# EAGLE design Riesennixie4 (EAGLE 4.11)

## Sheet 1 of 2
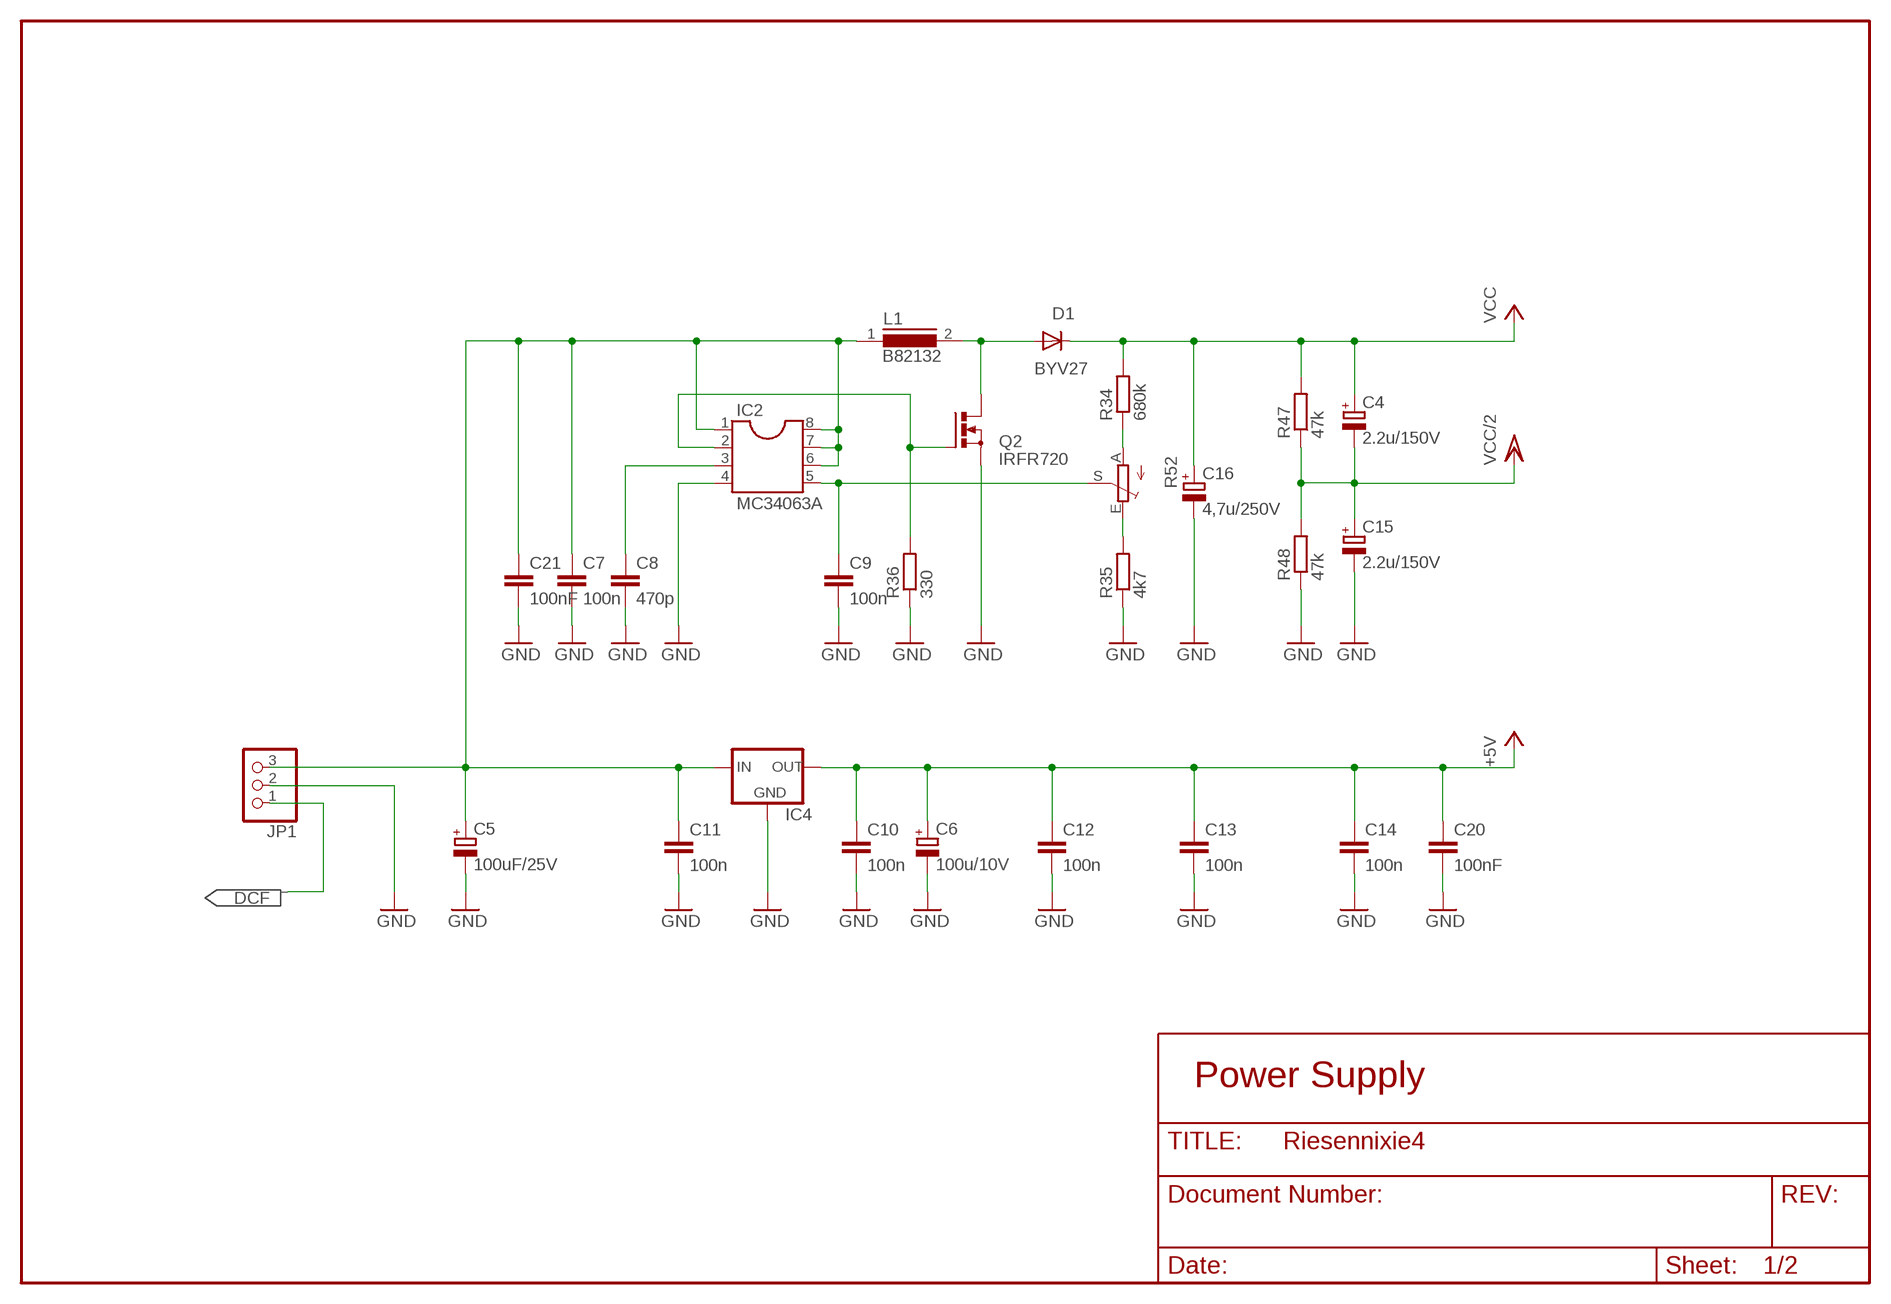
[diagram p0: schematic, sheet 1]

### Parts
C4  2.2u/150V  CPOL-EUE25-9AXIAL  [E25-9]
C5  100uF/25V  CPOL-EUE5-6  [E5-6]
C6  100u/10V  CPOL-EUE5-6  [E5-6]
C7  100n  C-EU025-024X044  [C025-024X044]
C8  470p  C-EU025-024X044  [C025-024X044]
C9  100n  C-EU025-024X044  [C025-024X044]
C10  100n  C-EU025-024X044  [C025-024X044]
C11  100n  C-EU025-024X044  [C025-024X044]
C12  100n  C-EU025-024X044  [C025-024X044]
C13  100n  C-EU025-024X044  [C025-024X044]
C14  100n  C-EU025-024X044  [C025-024X044]
C15  2.2u/150V  CPOL-EUE25-9AXIAL  [E25-9]
C16  4,7u/250V  CPOL-EUE25-10AXIAL  [E25-10]
C20  100nF  C-EU025-025X050  [C025-025X050]
C21  100nF  C-EUC1206  [C1206]
D1  BYV27  [SOD57-10]
IC2  MC34063A  DIL8  [DIL08]
IC4  78XXL  [78XXL]
JP1  PINHD-1X3  [1X03]
L1  B82132  [SUKW2-22]
Q2  IRFR720  PMOSFET_N  [TO220AHS]
R34  680k  R-EU_0204/7  [0204/7]
R35  4k7  R-EU_0204/7  [0204/7]
R36  330  R-EU_0204/7  [0204/7]
R47  47k  R-EU_0207/7  [0207/7]
R48  47k  R-EU_0207/7  [0207/7]
R52  TRIM_EU-CA6V  [CA6V]

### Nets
+5V: C6.+ C10.1 C12.1 C13.1 C14.1 C20.1 IC4.OUT ; also sheet 2
DCF: JP1.1 ; also sheet 2
GND: C5.- C6.- C7.2 C8.2 C9.2 C10.2 C11.2 C12.2 C13.2 C14.2 C15.- C16.- C20.2 C21.2 IC2.4 IC4.GND JP1.2 Q2.E(S) R35.1 R36.1 R48.1 ; also sheet 2
N$82: C8.1 IC2.3
N$83: IC2.2 Q2.B(G) R36.2
N$84: D1.A L1.2 Q2.C(D)
N$86: C9.1 IC2.5 R52.S
N$87: R34.1 R52.A
N$88: R35.2 R52.E
N$90: C5.+ C7.1 C11.1 C21.1 IC2.1 IC2.6 IC2.7 IC2.8 IC4.IN JP1.3 L1.1
VCC: C4.+ C16.+ D1.C R34.2 R47.2 ; also sheet 2
VCC/2: C4.- C15.+ R47.1 R48.2 ; also sheet 2

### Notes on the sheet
- Power Supply

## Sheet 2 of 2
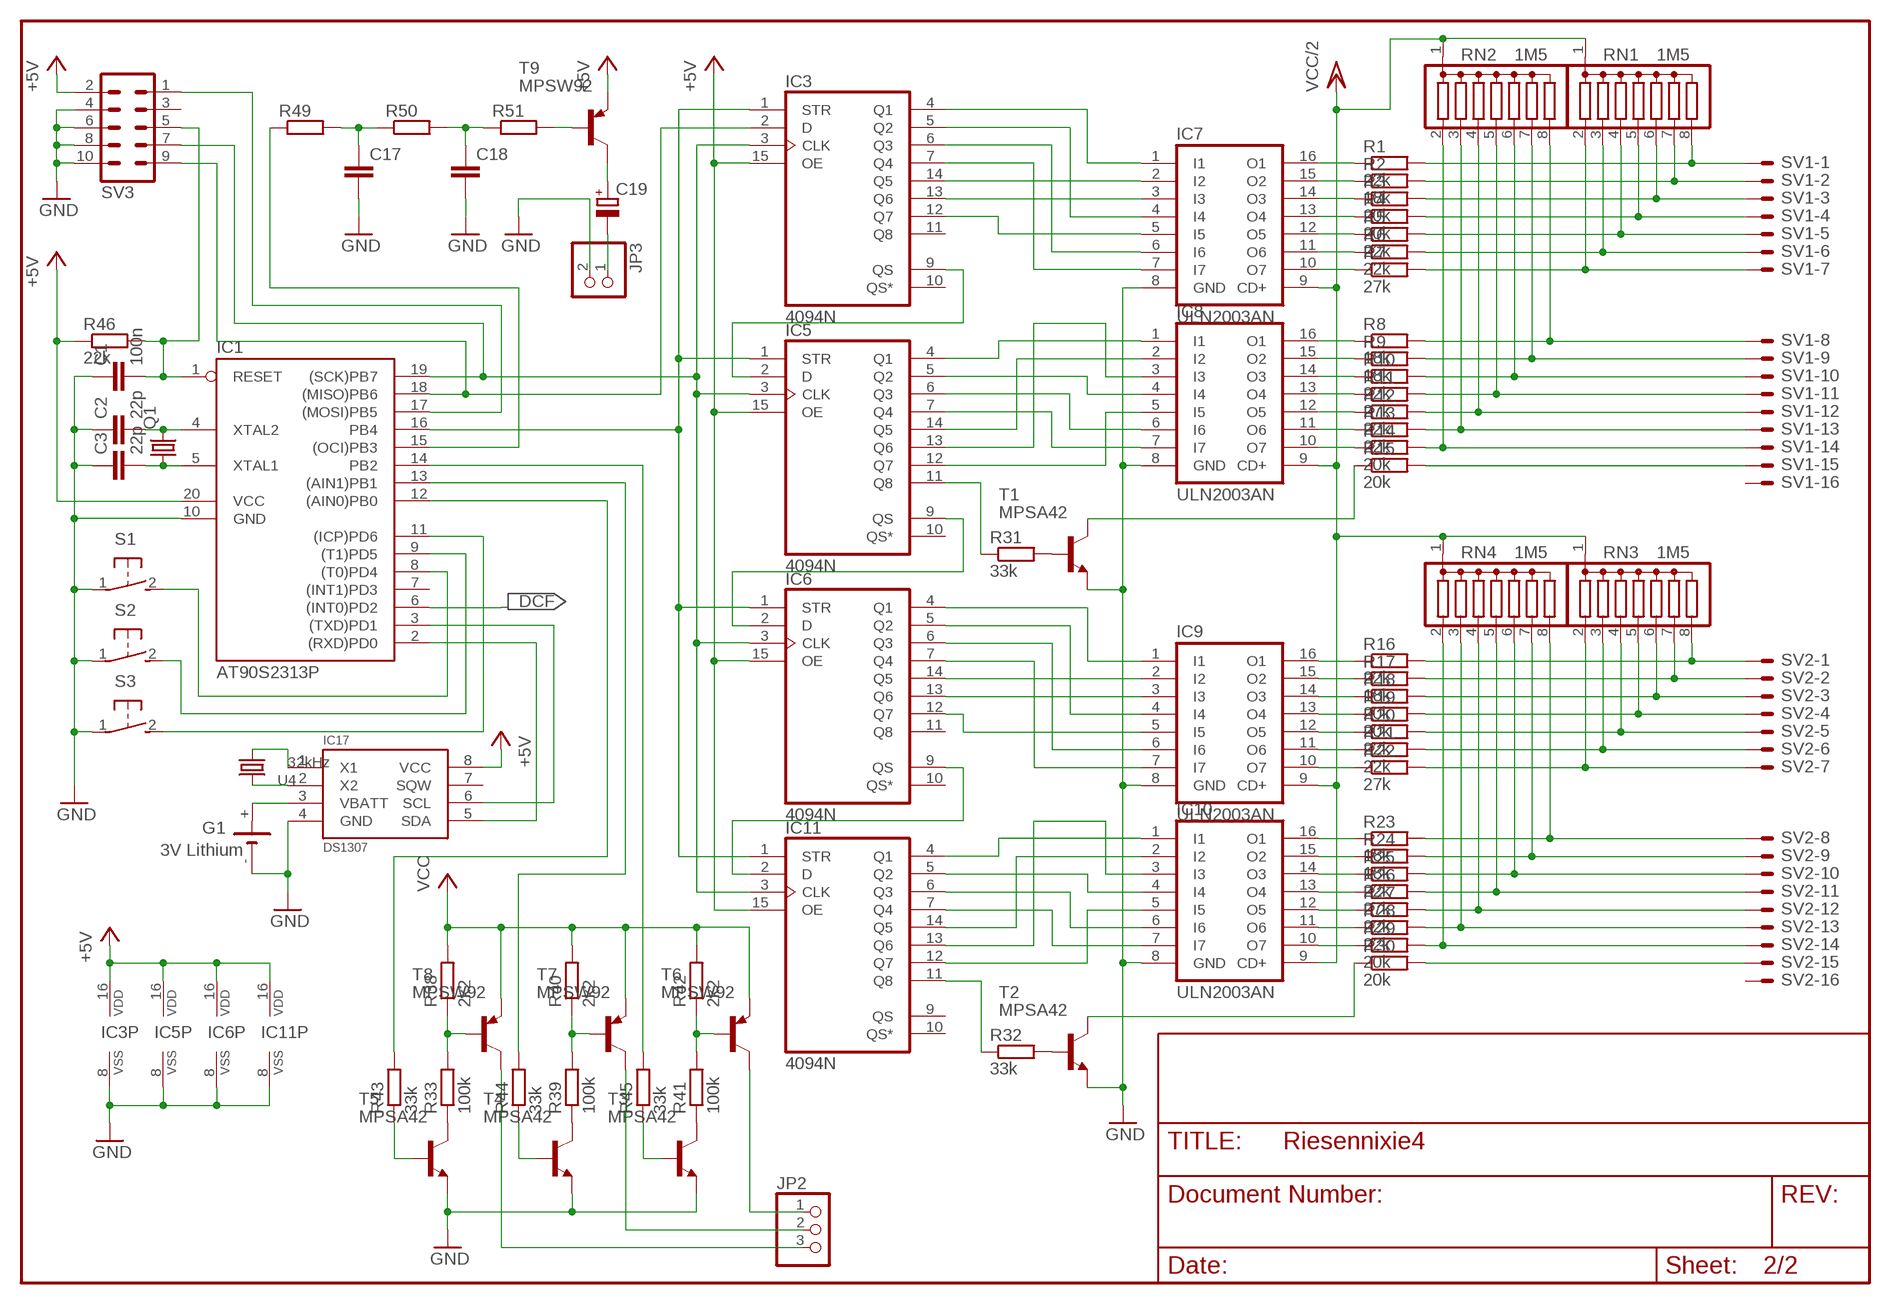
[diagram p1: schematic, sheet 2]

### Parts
C1  100n  C-EU025-025X050  [C025-025X050]
C2  22p  C-EU025-025X050  [C025-025X050]
C3  22p  C-EU025-025X050  [C025-025X050]
C17  C-EU025-025X050  [C025-025X050]
C18  C-EU025-025X050  [C025-025X050]
C19  CPOL-EUE2.5-6  [E2,5-6]
G1  3V Lithium  BR12XX  [BR12XX]
IC1  AT90S2313P  [DIL20]
IC3  4094N  [DIL16]
IC5  4094N  [DIL16]
IC6  4094N  [DIL16]
IC7  ULN2003AN  [DIL16]
IC8  ULN2003AN  [DIL16]
IC9  ULN2003AN  [DIL16]
IC10  ULN2003AN  [DIL16]
IC11  4094N  [DIL16]
IC17  DS1307  [SO08]
JP2  PINHD-1X3  [1X03]
JP3  PINHD-1X2  [1X02]
Q1  CRYTALHC49S  [HC49/S]
R1  22k  R-EU_0207/7  [0207/7]
R2  18k  R-EU_0207/7  [0207/7]
R3  20k  R-EU_0207/7  [0207/7]
R4  20k  R-EU_0207/7  [0207/7]
R5  22k  R-EU_0207/7  [0207/7]
R6  22k  R-EU_0207/7  [0207/7]
R7  27k  R-EU_0207/7  [0207/7]
R8  18k  R-EU_0207/7  [0207/7]
R9  18k  R-EU_0207/7  [0207/7]
R10  22k  R-EU_0207/7  [0207/7]
R11  27k  R-EU_0207/7  [0207/7]
R12  22k  R-EU_0207/7  [0207/7]
R13  22k  R-EU_0207/7  [0207/7]
R14  20k  R-EU_0207/7  [0207/7]
R15  20k  R-EU_0207/7  [0207/7]
R16  22k  R-EU_0207/7  [0207/7]
R17  18k  R-EU_0207/7  [0207/7]
R18  20k  R-EU_0207/7  [0207/7]
R19  20k  R-EU_0207/7  [0207/7]
R20  22k  R-EU_0207/7  [0207/7]
R21  22k  R-EU_0207/7  [0207/7]
R22  27k  R-EU_0207/7  [0207/7]
R23  18k  R-EU_0207/7  [0207/7]
R24  18k  R-EU_0207/7  [0207/7]
R25  22k  R-EU_0207/7  [0207/7]
R26  27k  R-EU_0207/7  [0207/7]
R27  22k  R-EU_0207/7  [0207/7]
R28  22k  R-EU_0207/7  [0207/7]
R29  20k  R-EU_0207/7  [0207/7]
R30  20k  R-EU_0207/7  [0207/7]
R31  33k  R-EU_0207/7  [0207/7]
R32  33k  R-EU_0207/7  [0207/7]
R33  100k  R-EU_0207/7  [0207/7]
R38  2k2  R-EU_0207/7  [0207/7]
R39  100k  R-EU_0207/7  [0207/7]
R40  2k2  R-EU_0207/7  [0207/7]
R41  100k  R-EU_0207/7  [0207/7]
R42  2k2  R-EU_0207/7  [0207/7]
R43  33k  R-EU_0204/7  [0204/7]
R44  33k  R-EU_0204/7  [0204/7]
R45  33k  R-EU_0204/7  [0204/7]
R46  22k  R-EU_0204/7  [0204/7]
R49  R-EU_0207/7  [0207/7]
R50  R-EU_0207/7  [0207/7]
R51  R-EU_0207/7  [0207/7]
RN1  1M5  G07R  [SIL8]
RN2  1M5  G07R  [SIL8]
RN3  1M5  G07R  [SIL8]
RN4  1M5  G07R  [SIL8]
S1  31-XX  [B3F-31XX]
S2  31-XX  [B3F-31XX]
S3  31-XX  [B3F-31XX]
SV1  ML16LE  [ML16L]
SV2  ML16LE  [ML16L]
SV3  ML10L  [ML10L]
T1  MPSA42  MPSA42-NPN-TO92-CBE  [TO92-CBE]
T2  MPSA42  MPSA42-NPN-TO92-CBE  [TO92-CBE]
T3  MPSA42  MPSA42-NPN-TO92-CBE  [TO92-CBE]
T4  MPSA42  MPSA42-NPN-TO92-CBE  [TO92-CBE]
T5  MPSA42  MPSA42-NPN-TO92-CBE  [TO92-CBE]
T6  MPSW92  MPSW92-PNP-TO92-CBE  [TO92-CBE]
T7  MPSW92  MPSW92-PNP-TO92-CBE  [TO92-CBE]
T8  MPSW92  MPSW92-PNP-TO92-CBE  [TO92-CBE]
T9  MPSW92  BC557B-PNP-TO92-EBC  [TO92-EBC]
U4  32kHz  TC26H  [TC26H]

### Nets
+5V: IC1.20(VCC) IC3.15(OE) IC3.16(VDD) IC5.15(OE) IC5.16(VDD) IC6.15(OE) IC6.16(VDD) IC11.15(OE) IC11.16(VDD) IC17.8(VCC) R46.1 SV3.2 T9.E ; also sheet 1
DCF: IC1.6((INT0)PD2) ; also sheet 1
GND: C1.1 C2.1 C3.1 C17.2 C18.2 G1.- IC1.10(GND) IC3.8(VSS) IC5.8(VSS) IC6.8(VSS) IC7.8(GND) IC8.8(GND) IC9.8(GND) IC10.8(GND) IC11.8(VSS) IC17.4(GND) JP3.2 S1.1(P) S2.1(P) S3.1(P) SV3.4 SV3.6 SV3.8 SV3.10 T1.E T2.E T3.E T4.E T5.E ; also sheet 1
N$1: IC7.16(O1) R1.1
N$2: IC7.15(O2) R2.1
N$3: IC7.14(O3) R3.1
N$4: IC7.13(O4) R4.1
N$5: IC7.12(O5) R5.1
N$6: IC7.11(O6) R6.1
N$7: IC7.10(O7) R7.1
N$8: IC8.16(O1) R8.1
N$9: IC8.15(O2) R9.1
N$10: IC8.14(O3) R10.1
N$11: IC8.13(O4) R11.1
N$12: IC8.12(O5) R12.1
N$13: IC8.11(O6) R13.1
N$14: IC8.10(O7) R14.1
N$15: IC9.16(O1) R16.1
N$16: IC9.15(O2) R17.1
N$17: IC9.14(O3) R18.1
N$18: IC9.13(O4) R19.1
N$19: IC9.12(O5) R20.1
N$20: IC9.11(O6) R21.1
N$21: IC9.10(O7) R22.1
N$22: IC10.16(O1) R23.1
N$23: IC10.15(O2) R24.1
N$24: IC10.14(O3) R25.1
N$25: IC10.13(O4) R26.1
N$26: IC10.12(O5) R27.1
N$27: IC10.11(O6) R28.1
N$28: IC10.10(O7) R29.1
N$29: R1.2 RN1.8 SV1.1
N$30: R2.2 RN1.7 SV1.2
N$31: R3.2 RN1.6 SV1.3
N$32: R4.2 RN1.5 SV1.4
N$33: R5.2 RN1.4 SV1.5
N$34: R6.2 RN1.3 SV1.6
N$35: R7.2 RN1.2 SV1.7
N$36: R8.2 RN2.8 SV1.8
N$37: R9.2 RN2.7 SV1.9
N$38: R10.2 RN2.6 SV1.10
N$39: R11.2 RN2.5 SV1.11
N$40: R12.2 RN2.4 SV1.12
N$41: R13.2 RN2.3 SV1.13
N$42: R14.2 RN2.2 SV1.14
N$43: R16.2 RN3.8 SV2.1
N$44: R17.2 RN3.7 SV2.2
N$45: R18.2 RN3.6 SV2.3
N$46: R19.2 RN3.5 SV2.4
N$47: R20.2 RN3.4 SV2.5
N$48: R21.2 RN3.3 SV2.6
N$49: R22.2 RN3.2 SV2.7
N$50: R23.2 RN4.8 SV2.8
N$51: R24.2 RN4.7 SV2.9
N$52: R25.2 RN4.6 SV2.10
N$53: R26.2 RN4.5 SV2.11
N$54: R27.2 RN4.4 SV2.12
N$55: R28.2 RN4.3 SV2.13
N$56: R29.2 RN4.2 SV2.14
N$57: IC3.7(Q4) IC7.7(I7)
N$58: IC3.6(Q3) IC7.6(I6)
N$59: IC3.5(Q2) IC7.4(I4)
N$60: IC3.4(Q1) IC7.1(I1)
N$61: IC3.12(Q7) IC7.5(I5)
N$62: IC3.13(Q6) IC7.3(I3)
N$63: IC3.14(Q5) IC7.2(I2)
N$64: IC5.14(Q5) IC8.2(I2)
N$65: IC5.4(Q1) IC8.1(I1)
N$66: IC5.7(Q4) IC8.7(I7)
N$67: IC5.6(Q3) IC8.6(I6)
N$68: IC5.5(Q2) IC8.4(I4)
N$69: IC5.12(Q7) IC8.5(I5)
N$70: IC5.13(Q6) IC8.3(I3)
N$71: IC6.4(Q1) IC9.1(I1)
N$72: IC6.5(Q2) IC9.4(I4)
N$73: IC6.6(Q3) IC9.6(I6)
N$74: IC6.7(Q4) IC9.7(I7)
N$75: IC6.14(Q5) IC9.2(I2)
N$76: IC6.13(Q6) IC9.3(I3)
N$77: IC6.12(Q7) IC9.5(I5)
N$78: IC10.1(I1) IC11.4(Q1)
N$79: IC10.4(I4) IC11.5(Q2)
N$80: IC10.6(I6) IC11.6(Q3)
N$81: IC10.7(I7) IC11.7(Q4)
N$85: IC10.2(I2) IC11.14(Q5)
N$89: IC10.3(I3) IC11.13(Q6)
N$91: IC10.5(I5) IC11.12(Q7)
N$92: R30.2 SV2.15
N$93: IC3.9(QS) IC5.2(D)
N$94: IC5.9(QS) IC6.2(D)
N$95: IC6.9(QS) IC11.2(D)
N$96: IC1.19((SCK)PB7) IC3.3(CLK) IC5.3(CLK) IC6.3(CLK) IC11.3(CLK) SV3.7
N$97: IC1.16(PB4) IC3.1(STR) IC5.1(STR) IC6.1(STR) IC11.1(STR)
N$98: R15.1 T1.C
N$99: R30.1 T2.C
N$100: R31.2 T1.B
N$101: R32.2 T2.B
N$102: IC5.11(Q8) R31.1
N$103: IC11.11(Q8) R32.1
N$104: R33.1 T5.C
N$105: R33.2 R38.1 T8.B
N$106: R39.1 T4.C
N$107: R39.2 R40.1 T7.B
N$108: R41.1 T3.C
N$109: R41.2 R42.1 T6.B
N$110: R43.1 T5.B
N$111: R44.1 T4.B
N$112: JP2.3 T8.C
N$113: JP2.2 T7.C
N$114: JP2.1 T6.C
N$115: R45.1 T3.B
N$116: R15.2 SV1.15
N$117: C1.2 IC1.1(RESET) R46.2 SV3.5
N$118: IC1.11((ICP)PD6) S3.2(S)
N$119: IC1.14(PB2) R45.2
N$120: IC1.13((AIN1)PB1) R44.2
N$121: IC1.12((AIN0)PB0) R43.2
N$122: IC1.18((MISO)PB6) IC3.2(D) SV3.9
N$123: IC17.2(X2) U4.2
N$124: IC1.9((T1)PD5) S2.2(S)
N$125: C2.2 IC1.4(XTAL2) Q1.2
N$126: C3.2 IC1.5(XTAL1) Q1.1
N$127: IC1.8((T0)PD4) S1.2(S)
N$128: C17.1 R49.2 R50.1
N$129: R51.2 T9.B
N$130: C18.1 R50.2 R51.1
N$131: C19.+ T9.C
N$132: C19.- JP3.1
N$133: IC1.15((OCI)PB3) R49.1
N$134: IC1.17((MOSI)PB5) SV3.1
N$135: IC17.1(X1) U4.1
N$136: G1.+ IC17.3(VBATT)
N$137: IC1.2((RXD)PD0) IC17.5(SDA)
N$138: IC1.3((TXD)PD1) IC17.6(SCL)
VCC: R38.2 R40.2 R42.2 T6.E T7.E T8.E ; also sheet 1
VCC/2: IC7.9(CD+) IC8.9(CD+) IC9.9(CD+) IC10.9(CD+) RN1.1 RN2.1 RN3.1 RN4.1 ; also sheet 1
Unconnected: IC1.7((INT1)PD3) IC3.10(QS*) IC3.11(Q8) IC5.10(QS*) IC6.10(QS*) IC6.11(Q8) IC11.9(QS) IC11.10(QS*) IC17.7(SQW) SV1.16 SV2.16 SV3.3

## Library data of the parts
C1-C3 C7-C14 C17 C18 C20 C21 = rcl:C-EU: CAPACITOR, European symbol
C4-C6 C15 C16 C19 = rcl:CPOL-EU: POLARIZED CAPACITOR, European symbol
D1 = diode:BYV27: DIODE
G1 = battery:BR12XX
IC1 = atmel:AT90S2313: MICROCONTROLLER 2 Kbytes FLASH 128 bytes SRAM 128 bytes EEPROM UART
IC2 = ic-package:DIL8: Dual In Line
IC3 IC5 IC6 IC11 = 40xx:4094: 8-stage SHIFT/STORE REGISTER, tri-state
IC4 = v-reg:78XXL: VOLTAGE REGULATOR
IC7-IC10 = uln-udn:ULN2003A: DRIVER ARRAY
IC17 = PUMP:DS1307
JP1 JP2 = pinhead:PINHD-1X3: PIN HEADER
JP3 = pinhead:PINHD-1X2: PIN HEADER
L1 = inductors:B82132: INDUCTOR
Q1 = crystal:CRYTAL: CRYSTAL
Q2 = transistor-power:PMOSFET_N: Power MOSFET N-Channel
R1-R36 R38-R51 = rcl:R-EU_: RESISTOR, European symbol
R52 = pot:TRIM_EU-: POTENTIOMETER
RN1-RN4 = resistor-sil:G07R: SIL RESISTOR
S1-S3 = switch-omron:31-XX: OMRON SWITCH
SV1 SV2 = con-harting-ml:ML16?E: HARTING
SV3 = con-harting-ml:ML10: HARTING
T1-T5 = transistor:*-NPN-: NPN Transistror
T6-T9 = transistor:*-PNP-: PNP Transistror
U4 = QUARTZ:TC26H

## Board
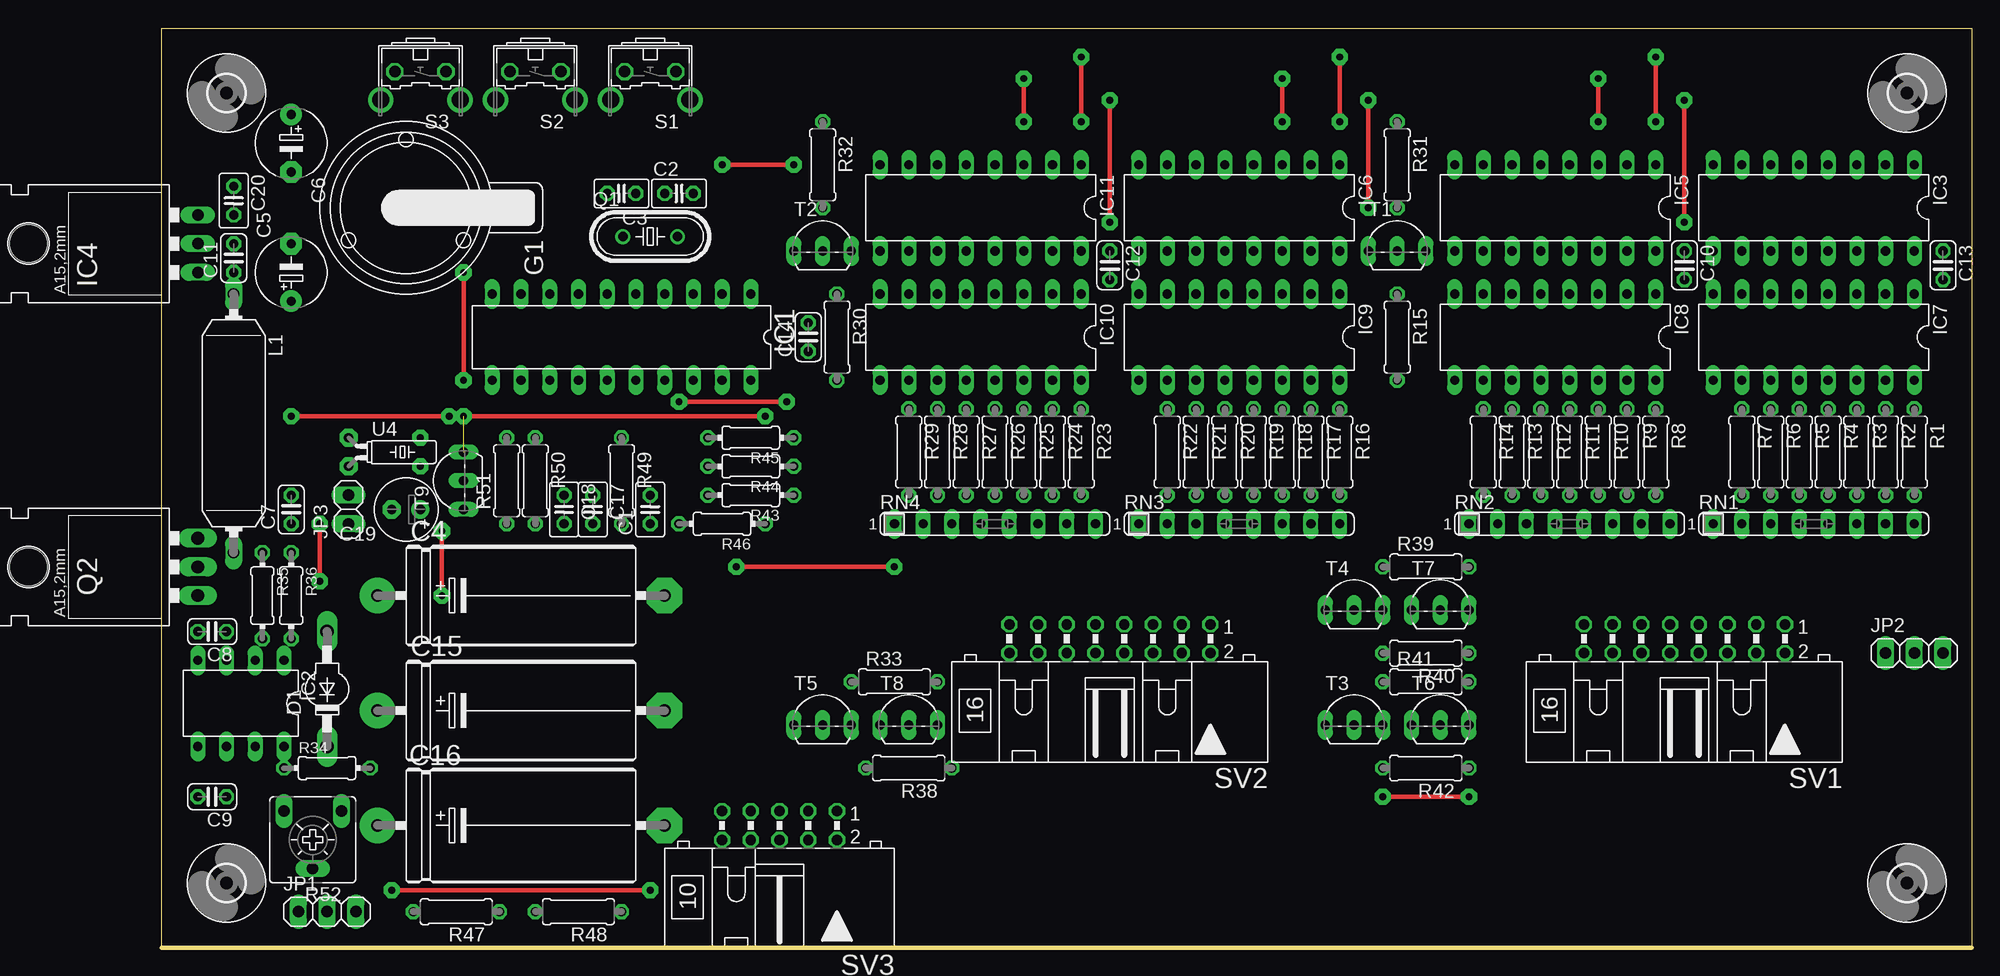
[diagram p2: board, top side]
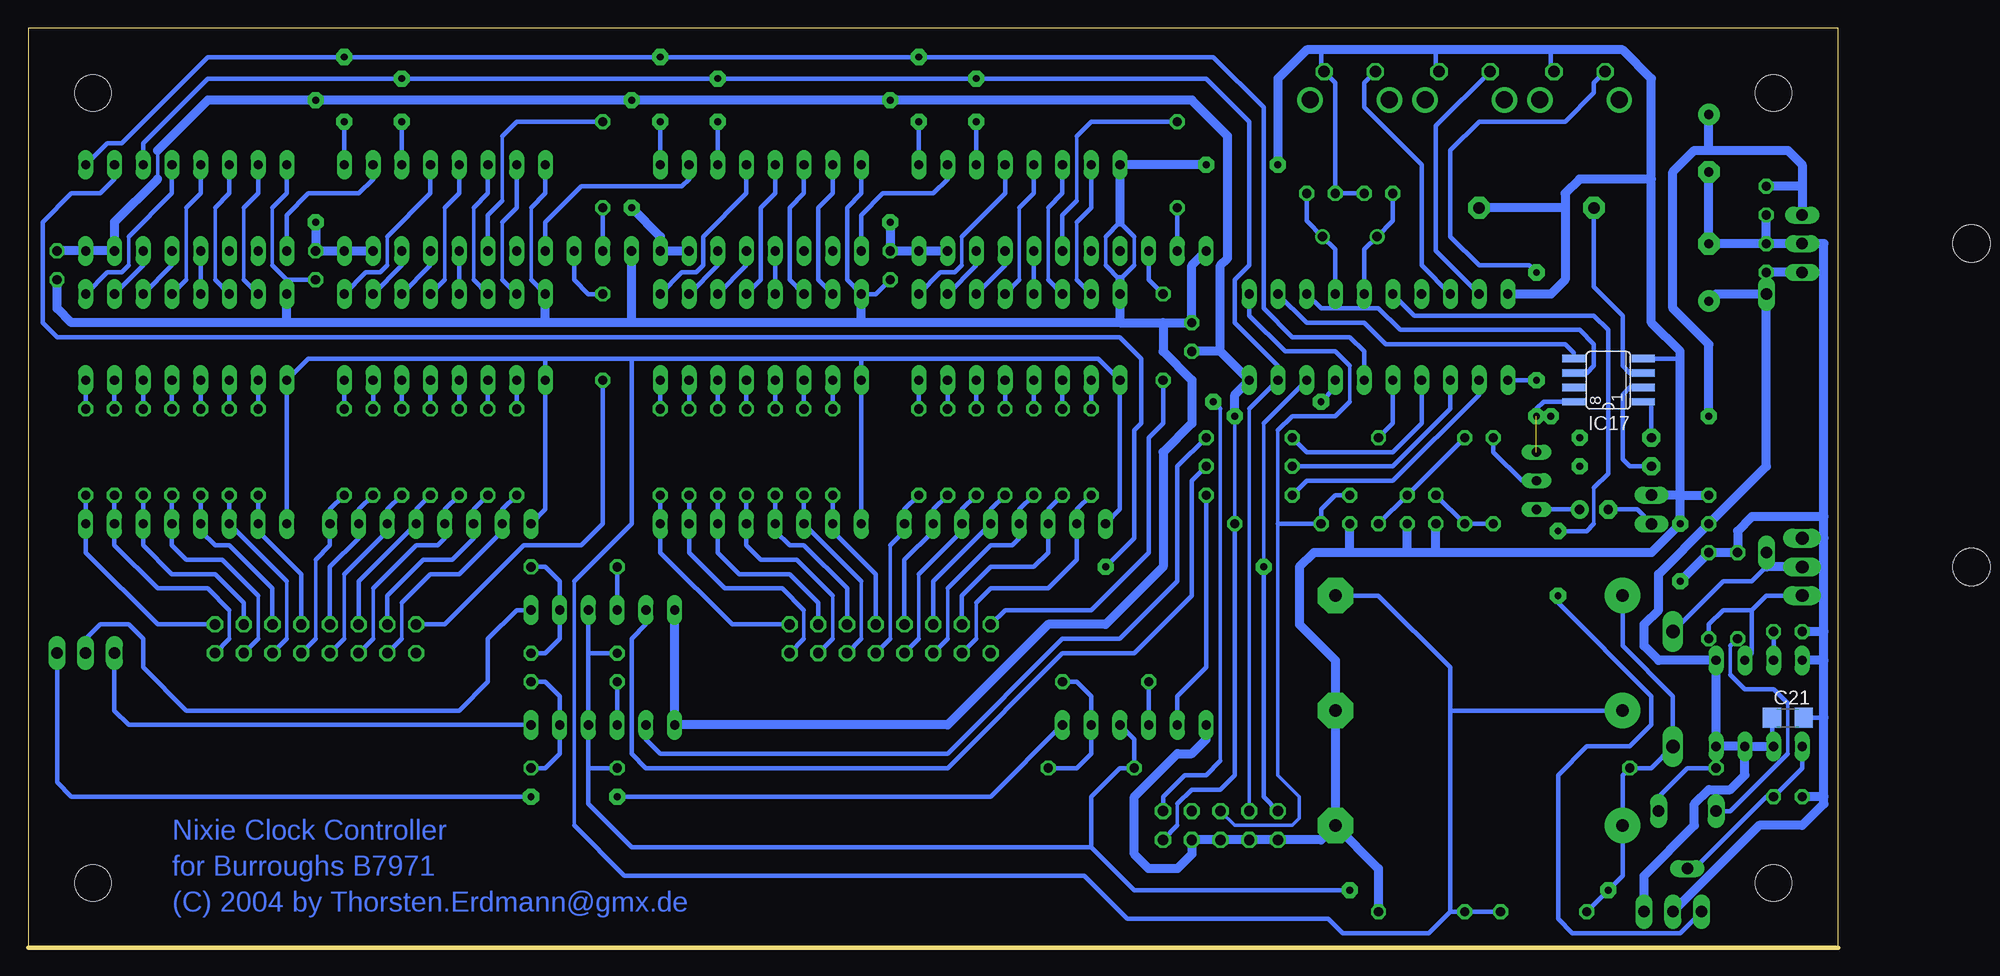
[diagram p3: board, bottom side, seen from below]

Size 160.02 x 81.28 mm. Coordinates in mm from the lower left corner, seen from the top.
Outline: 0,81.28 160.02,81.28 160.02,0 0,0 0,81.28
Copper layers (1*16): Top 0.035mm / dielectric 1.5mm / Bottom 0.035mm
Design rules "default": minimum track width 10mil, minimum drill 24mil, track to track 8mil, track to pad 8mil, pad to pad 8mil, via to via 8mil, smd to smd 8mil, copper to edge 40mil, drill to drill 8mil, minimum pad ring 10mil, minimum via ring 8mil, stop-mask expansion 4mil, vias tented up to drill 0mil, thermal gap 10mil

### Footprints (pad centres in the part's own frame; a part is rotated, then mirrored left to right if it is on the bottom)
C025-025X050 = drill 0.813 octagon: 1 -1.27,0; 2 1.27,0
E25-9 = drill 1.118 pad 3.15 round: + -12.7,0 | drill 1.118 pad 3.15 octagon: - 12.7,0
E5-6 = drill 0.813 pad 1.905 round: + -2.54,0 | drill 0.813 pad 1.905 octagon: - 2.54,0
C025-024X044 = drill 0.813 octagon: 1 -1.27,0; 2 1.27,0
E25-10 = drill 1.118 pad 3.15 round: + -12.7,0 | drill 1.118 pad 3.15 octagon: - 12.7,0
E2,5-6 = drill 0.813 pad 1.6 round: + -1.27,0 | drill 0.813 pad 1.6 octagon: - 1.27,0
C1206 = smd 1.6 x 1.8: 1 -1.4,0; 2 1.4,0
SOD57-10 = drill 1.194 long: A 5.08,0; C -5.08,0
BR12XX = drill 1.016 pad 1.93 octagon: + 0,0; - 0,10.16
DIL20 = drill 0.813 long: 1 -11.43,-3.81; 2 -8.89,-3.81; 3 -6.35,-3.81; 4 -3.81,-3.81; 5 -1.27,-3.81; 6 1.27,-3.81; 7 3.81,-3.81; 8 6.35,-3.81; 9 8.89,-3.81; 10 11.43,-3.81; 11 11.43,3.81; 12 8.89,3.81; 13 6.35,3.81; 14 3.81,3.81; 15 1.27,3.81; 16 -1.27,3.81; 17 -3.81,3.81; 18 -6.35,3.81; 19 -8.89,3.81; 20 -11.43,3.81
DIL08 = drill 0.813 long: 1 -3.81,-3.81; 2 -1.27,-3.81; 3 1.27,-3.81; 4 3.81,-3.81; 5 3.81,3.81; 6 1.27,3.81; 7 -1.27,3.81; 8 -3.81,3.81
DIL16 = drill 0.813 long: 1 -8.89,-3.81; 2 -6.35,-3.81; 3 -3.81,-3.81; 4 -1.27,-3.81; 5 1.27,-3.81; 6 3.81,-3.81; 7 6.35,-3.81; 8 8.89,-3.81; 9 8.89,3.81; 10 6.35,3.81; 11 3.81,3.81; 12 1.27,3.81; 13 -1.27,3.81; 14 -3.81,3.81; 15 -6.35,3.81; 16 -8.89,3.81
78XXL = drill 1.016 long: GND 0,-3.81; IN -2.54,-3.81; OUT 2.54,-3.81 | hole 3.302: 0,11.176
SO08 = smd 0.66 x 2.032: 1 -1.905,-3.073; 2 -0.635,-3.073; 3 0.635,-3.073; 4 1.905,-3.073; 5 1.905,3.073; 6 0.635,3.073; 7 -0.635,3.073; 8 -1.905,3.073
1X03 = drill 1.016 long: 1 -2.54,0; 2 0,0; 3 2.54,0
1X02 = drill 1.016 long: 1 -1.27,0; 2 1.27,0
SUKW2-22 = drill 1.016 long: 1 -11.43,0; 2 11.43,0
HC49/S = drill 0.813 round: 1 -2.413,0; 2 2.413,0
TO220AHS = drill 1.118 long: B -2.54,-3.81; C 0,-3.81; E 2.54,-3.81 | hole 3.302: 0,11.176
0207/7 = drill 0.813 octagon: 1 -3.81,0; 2 3.81,0
0204/7 = drill 0.813 octagon: 1 -3.81,0; 2 3.81,0
CA6V = drill 1.016 long: A -2.54,-2.54; E 2.54,-2.54; S 0,2.54
SIL8 = drill 0.813 long: 1 -8.89,0; 2 -6.35,0; 3 -3.81,0; 4 -1.27,0; 5 1.27,0; 6 3.81,0; 7 6.35,0; 8 8.89,0
B3F-31XX = drill 1.016 octagon: 1 -2.261,-1.245; 2 2.261,-1.245 | drill 1.499 pad 2.159 round: 3 -3.505,1.245; 4 3.505,1.245
ML16L = drill 0.914 octagon: 1 -8.89,-1.27; 2 -8.89,1.27; 3 -6.35,-1.27; 4 -6.35,1.27; 5 -3.81,-1.27; 6 -3.81,1.27; 7 -1.27,-1.27; 8 -1.27,1.27; 9 1.27,-1.27; 10 1.27,1.27; 11 3.81,-1.27; 12 3.81,1.27; 13 6.35,-1.27; 14 6.35,1.27; 15 8.89,-1.27; 16 8.89,1.27
ML10L = drill 0.914 octagon: 1 -5.08,-1.27; 2 -5.08,1.27; 3 -2.54,-1.27; 4 -2.54,1.27; 5 0,-1.27; 6 0,1.27; 7 2.54,-1.27; 8 2.54,1.27; 9 5.08,-1.27; 10 5.08,1.27
TO92-CBE = drill 0.813 long: B 0,0; C 2.54,0; E -2.54,0
TO92-EBC = drill 0.813 long: B 0,-1.27; C -2.54,-1.27; E 2.54,-1.27
TC26H = drill 0.813 pad 1.6 octagon: 1 -1.27,0; 2 1.27,0
3,2 = hole 3.2: 0,0

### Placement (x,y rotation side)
C1  43.18,38.73 90 top
C2  45.72,66.68 0 top
C3  40.64,66.68 180 top
C4  31.75,31.12 0 top
C5  11.43,59.69 90 top
C6  11.43,71.12 270 top
C7  11.43,38.73 90 top
C8  4.45,27.94 180 top
C9  4.45,13.33 180 top
C10  134.62,60.32 270 top
C11  6.35,60.96 90 top
C12  83.82,60.32 270 top
C13  157.48,60.32 270 top
C14  57.15,53.98 90 top
C15  31.75,20.96 0 top
C16  31.75,10.79 0 top
C17  38.1,38.73 270 top
C18  35.56,38.73 270 top
C19  21.59,38.73 180 top
C20  6.35,66.04 270 top
C21  4.45,20.32 0 bottom
D1  14.61,22.86 90 top
G1  21.59,65.41 270 top
IC1  40.64,53.98 180 top
IC2  6.98,21.59 180 top
IC3  146.05,65.41 180 top
IC4  -0.64,62.23 90 top
IC5  123.19,65.41 180 top
IC6  95.25,65.41 180 top
IC7  146.05,53.98 180 top
IC8  123.19,53.98 180 top
IC9  95.25,53.98 180 top
IC10  72.39,53.98 180 top
IC11  72.39,65.41 180 top
IC17  20.32,50.16 90 bottom
JP1  14.61,3.17 0 top
JP2  154.94,26.04 0 top
JP3  16.51,38.73 90 top
L1  6.35,46.35 270 top
Q1  43.18,62.86 0 top
Q2  -0.64,33.66 90 top
R1  154.94,43.81 270 top
R2  152.4,43.81 270 top
R3  149.86,43.81 270 top
R4  147.32,43.81 270 top
R5  144.78,43.81 270 top
R6  142.24,43.81 270 top
R7  139.7,43.81 270 top
R8  132.08,43.81 270 top
R9  129.54,43.81 270 top
R10  127,43.81 270 top
R11  124.46,43.81 270 top
R12  121.92,43.81 270 top
R13  119.38,43.81 270 top
R14  116.84,43.81 270 top
R15  109.22,53.98 270 top
R16  104.14,43.81 270 top
R17  101.6,43.81 270 top
R18  99.06,43.81 270 top
R19  96.52,43.81 270 top
R20  93.98,43.81 270 top
R21  91.44,43.81 270 top
R22  88.9,43.81 270 top
R23  81.28,43.81 270 top
R24  78.74,43.81 270 top
R25  76.2,43.81 270 top
R26  73.66,43.81 270 top
R27  71.12,43.81 270 top
R28  68.58,43.81 270 top
R29  66.04,43.81 270 top
R30  59.69,53.98 270 top
R31  109.22,69.22 270 top
R32  58.42,69.22 270 top
R33  64.77,23.5 0 top
R34  14.61,15.88 0 top
R35  8.89,31.12 270 top
R36  11.43,31.12 270 top
R38  66.04,15.88 180 top
R39  111.76,33.66 0 top
R40  111.76,26.04 180 top
R41  111.76,23.5 0 top
R42  111.76,15.88 180 top
R43  52.07,40 180 top
R44  52.07,42.54 180 top
R45  52.07,45.09 180 top
R46  49.53,37.46 180 top
R47  26.04,3.17 180 top
R48  36.83,3.17 180 top
R49  40.64,41.27 270 top
R50  33.02,41.27 270 top
R51  30.48,41.27 90 top
R52  13.33,9.53 180 top
RN1  146.05,37.46 0 top
RN2  124.46,37.46 0 top
RN3  95.25,37.46 0 top
RN4  73.66,37.46 0 top
S1  43.18,76.2 180 top
S2  33.02,76.2 180 top
S3  22.86,76.2 180 top
SV1  134.62,27.31 180 top
SV2  83.82,27.31 180 top
SV3  54.61,10.79 180 top
T1  109.22,61.59 0 top
T2  58.42,61.59 0 top
T3  105.41,19.69 0 top
T4  105.41,29.85 0 top
T5  58.42,19.69 0 top
T6  113.03,19.69 0 top
T7  113.03,29.85 0 top
T8  66.04,19.69 0 top
T9  25.4,41.27 90 top
U4  16.51,43.81 270 top
U$1  [3,2]  5.71,5.71 0 top
U$2  [3,2]  5.71,75.57 0 top
U$3  [3,2]  154.3,75.57 0 top
U$4  [3,2]  154.3,5.71 0 top

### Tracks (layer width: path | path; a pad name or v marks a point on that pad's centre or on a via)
+5V  (via drill 0.61 pad 1.42)  (1 unrouted)
  Top 0.406: v83.82,74.93 v83.82,64.14 | v106.68,74.93 v106.68,65.41 | v134.62,74.93 v134.62,64.14 | v26.67,46.99 v53.34,46.99 | v11.43,46.99 v25.4,46.99
  Bottom 0.305: 148.59,70.48 148.59,67.95 | 58.42,12.7 58.42,10.79 | v53.34,46.99 R46.1
  Bottom 0.406: 58.42,10.79 SV3.2 | 58.42,12.7 57.15,13.97 54.61,13.97 53.34,15.24 R46.1 | IC17.8 26.04,48.26 26.67,47.62 v26.67,46.99
  Bottom 0.813: v106.68,65.41 104.14,62.86 IC6.16 IC6.15 | IC11.15 IC11.16 C12.1 v83.82,64.14 | IC5.15 IC5.16 C10.1 v134.62,64.14 | 148.59,70.48 144.14,74.93 v134.62,74.93 v106.68,74.93 v83.82,74.93 57.15,74.93 53.98,71.76 53.98,60.96 54.61,60.32 54.61,52.7 | 148.59,67.95 152.4,64.14 IC3.15 IC3.16 C13.1 | 3.17,67.31 3.17,69.22 4.45,70.48 11.43,70.48 | 3.17,67.31 IC4.OUT | 54.61,52.7 IC1.20 53.34,48.89 v53.34,46.99 | 54.61,52.7 C14.1 | v25.4,46.99 v26.67,46.99 | v11.43,46.99 11.43,53.34 14.61,56.52 14.61,68.58 12.7,70.48 11.43,70.48 | 3.17,67.31 C20.1 | 11.43,70.48 C6.+
DCF  (via drill 0.61 pad 1.42)
  Top 0.406: v24.77,31.12 v24.77,36.83
  Bottom 0.305: 21.59,37.46 21.59,40.64
  Bottom 0.406: IC1.6 37.46,55.88 21.59,55.88 20.32,54.61 20.32,41.91 21.59,40.64 | 21.59,37.46 22.23,36.83 v24.77,36.83 | v24.77,31.12 24.77,30.48 16.51,22.23 16.51,19.69 18.42,17.78 22.23,17.78 24.77,15.24 24.77,2.54 23.5,1.27 13.97,1.27 JP1.1
GND  (via drill 0.61 pad 1.42)
  Top 0.406: v49.53,69.22 v55.88,69.22 | v13.97,32.38 v13.97,37.46
  Bottom 0.305: 115.57,59.05 115.57,65.41 | 138.43,60.32 138.43,65.41 | 64.77,62.86 64.77,60.32 | 62.23,62.86 62.23,60.32
  Bottom 0.406: IC8.8 115.57,59.05 | IC5.8 114.3,66.68 115.57,65.41 | IC3.8 137.16,66.68 138.43,65.41 | 137.16,59.05 138.43,60.32 | IC7.8 137.16,59.05 | 64.77,60.32 63.5,59.05 62.23,60.32 | 64.77,62.86 63.5,64.14 62.23,62.86 | IC6.8 86.36,66.68 87.63,65.41 87.63,59.05 IC9.8 85.09,57.78 C12.2 | 137.16,59.05 C10.2 | C3.1 C2.1 44.45,76.45 S1.1 45.72,77.72 45.72,79.38 | S3.1 25.4,77.72 25.4,79.38 | S2.1 35.56,77.72 35.56,79.38 | 13.97,52.07 IC17.4 | 1.27,20.32 C21.2
  Bottom 0.813: 63.5,55.24 IC10.8 63.5,59.05 | 114.3,55.24 137.16,55.24 | 86.36,55.24 IC9.8 | 63.5,55.24 86.36,55.24 | 114.3,55.24 IC8.8 | 137.16,55.24 IC7.8 | 63.5,64.14 IC11.8 v55.88,69.22 | 86.36,55.24 106.68,55.24 | 106.68,55.24 114.3,55.24 | 106.68,55.24 T1.E | 1.27,13.33 1.27,20.32 1.27,25.4 | 1.27,25.4 1.27,27.94 | 1.27,27.94 1.27,36.2 | 1.27,36.2 1.27,38.1 | 1.27,38.1 1.27,62.23 IC4.GND C11.2 | 1.27,13.33 C9.2 | C6.- C5.- C11.2 | C13.2 157.48,56.52 156.21,55.24 137.16,55.24 | T4.E T3.E 78.74,19.69 69.85,28.58 64.77,28.58 59.69,33.66 59.69,43.81 57.15,46.35 57.15,50.16 59.69,52.7 59.69,55.24 | IC1.10 25.4,57.78 24.13,59.05 24.13,65.41 | 16.51,67.95 16.51,76.84 19.05,79.38 25.4,79.38 35.56,79.38 45.72,79.38 46.99,79.38 49.53,76.84 v49.53,69.22 | 24.13,65.41 G1.- | 13.97,40 JP3.2 | 13.97,40 v13.97,37.46 16.51,34.92 35.56,34.92 | 43.18,34.92 C1.1 | 35.56,34.92 38.1,34.92 | 38.1,34.92 43.18,34.92 | 38.1,34.92 C17.2 | 35.56,34.92 C18.2 | C16.- 45.72,9.53 SV3.10 SV3.8 SV3.6 SV3.4 57.15,8.26 58.42,6.98 60.96,6.98 62.23,8.26 62.23,13.33 58.42,17.15 57.15,17.15 55.88,18.42 T5.E | 43.18,34.92 46.35,34.92 47.62,33.66 47.62,28.58 44.45,25.4 C15.- C16.- | T2.E 57.15,60.32 C14.2 59.69,55.24 | 63.5,55.24 59.69,55.24 | R48.1 40.64,6.98 C16.- | 13.97,40 13.97,52.07 13.97,52.7 16.51,55.24 16.51,67.95 | 16.51,67.95 22.86,67.95 24.13,66.68 24.13,65.41 | 1.27,25.4 IC2.4 | 1.27,36.2 Q2.E | 1.27,27.94 C8.2 | 1.27,38.1 7.62,38.1 8.89,36.83 R35.1 R36.1 v13.97,32.38 | JP1.2 6.98,10.79 3.17,10.79 1.27,12.7 1.27,13.33 | 13.97,40 C7.2 | C11.2 C20.2
N$1
  Bottom 0.406: R1.1 IC7.16
N$2
  Bottom 0.406: R2.1 IC7.15
N$3
  Bottom 0.406: R3.1 IC7.14
N$4
  Bottom 0.406: R4.1 IC7.13
N$5
  Bottom 0.406: R5.1 IC7.12
N$6
  Bottom 0.406: R6.1 IC7.11
N$7
  Bottom 0.406: R7.1 IC7.10
N$8
  Bottom 0.406: R8.1 IC8.16
N$9
  Bottom 0.406: R9.1 IC8.15
N$10
  Bottom 0.406: R10.1 IC8.14
N$11
  Bottom 0.406: R11.1 IC8.13
N$12
  Bottom 0.406: R12.1 IC8.12
N$13
  Bottom 0.406: R13.1 IC8.11
N$14
  Bottom 0.406: R14.1 IC8.10
N$15
  Bottom 0.406: R16.1 IC9.16
N$16
  Bottom 0.406: R17.1 IC9.15
N$17
  Bottom 0.406: R18.1 IC9.14
N$18
  Bottom 0.406: R19.1 IC9.13
N$19
  Bottom 0.406: R20.1 IC9.12
N$20
  Bottom 0.406: R21.1 IC9.11
N$21
  Bottom 0.406: R22.1 IC9.10
N$22
  Bottom 0.406: R23.1 IC10.16
N$23
  Bottom 0.406: R24.1 IC10.15
N$24
  Bottom 0.406: R25.1 IC10.14
N$25
  Bottom 0.406: R26.1 IC10.13
N$26
  Bottom 0.406: R27.1 IC10.12
N$27
  Bottom 0.406: R28.1 IC10.11
N$28
  Bottom 0.406: R29.1 IC10.10
N$29
  Bottom 0.406: SV1.1 148.59,28.58 154.94,34.92 RN1.8 R1.2
N$30
  Bottom 0.305: 142.24,27.31 142.24,29.85
  Bottom 0.406: 142.24,27.31 SV1.2 | 142.24,29.85 144.14,31.75 148.59,31.75 152.4,35.56 RN1.7 R2.2
N$31
  Bottom 0.406: SV1.3 140.97,30.48 143.51,33.02 147.32,33.02 149.86,35.56 RN1.6 R3.2
N$32
  Bottom 0.305: 139.7,27.31 139.7,31.12
  Bottom 0.406: 139.7,27.31 SV1.4 | 139.7,31.12 142.88,34.29 146.05,34.29 147.32,35.56 RN1.5 R4.2
N$33
  Bottom 0.406: SV1.5 138.43,31.75 142.24,35.56 143.51,35.56 144.78,36.83 RN1.4 R5.2
N$34
  Bottom 0.305: 137.16,27.31 137.16,32.38
  Bottom 0.406: 137.16,27.31 SV1.6 | 137.16,32.38 RN1.3 R6.2
N$35
  Bottom 0.406: SV1.7 135.89,33.02 139.7,36.83 RN1.2 R7.2
N$36
  Bottom 0.305: 134.62,27.31 134.62,34.29
  Bottom 0.406: 134.62,27.31 SV1.8 | 134.62,34.29 133.35,35.56 RN2.8 133.35,38.73 R8.2
N$37
  Bottom 0.406: SV1.9 133.35,33.66 130.81,36.2 RN2.7 130.81,38.73 R9.2
N$38
  Bottom 0.305: 132.08,27.31 132.08,33.02
  Bottom 0.406: 132.08,27.31 SV1.10 | 132.08,33.02 128.27,36.83 RN2.6 128.27,38.73 R10.2
N$39
  Bottom 0.406: SV1.11 130.81,32.38 RN2.5 125.73,38.73 R11.2
N$40
  Bottom 0.305: 129.54,27.31 129.54,31.75
  Bottom 0.406: 129.54,27.31 SV1.12 | 129.54,31.75 125.73,35.56 123.83,35.56 123.19,36.2 RN2.4 123.19,38.73 R12.2
N$41
  Bottom 0.406: SV1.13 128.27,31.12 125.09,34.29 122.56,34.29 120.65,36.2 RN2.3 120.65,38.73 R13.2
N$42
  Bottom 0.305: 127,30.48 127,27.31
  Bottom 0.406: 127,27.31 SV1.14 | 127,30.48 124.46,33.02 121.92,33.02 118.11,36.83 RN2.2 118.11,38.73 R14.2
N$43
  Bottom 0.406: SV2.1 97.79,28.58 104.14,34.92 RN3.8 R16.2
N$44
  Bottom 0.305: 91.44,27.31 91.44,29.85
  Bottom 0.406: 91.44,27.31 SV2.2 | 91.44,29.85 93.34,31.75 98.43,31.75 101.6,34.92 RN3.7 R17.2
N$45
  Bottom 0.406: SV2.3 90.17,30.48 92.71,33.02 97.16,33.02 99.06,34.92 RN3.6 R18.2
N$46
  Bottom 0.305: 88.9,27.31 88.9,31.12
  Bottom 0.406: 88.9,27.31 SV2.4 | 88.9,31.12 92.08,34.29 95.25,34.29 96.52,35.56 RN3.5 R19.2
N$47
  Bottom 0.406: SV2.5 87.63,31.75 91.44,35.56 92.71,35.56 93.98,36.83 RN3.4 R20.2
N$48
  Bottom 0.305: 86.36,27.31 86.36,32.38
  Bottom 0.406: 86.36,27.31 SV2.6 | 86.36,32.38 RN3.3 R21.2
N$49
  Bottom 0.406: SV2.7 85.09,33.02 88.9,36.83 RN3.2 R22.2
N$50
  Bottom 0.305: 83.82,27.31 83.82,35.56
  Bottom 0.406: 83.82,27.31 SV2.8 | 83.82,35.56 82.55,36.83 RN4.8 82.55,38.73 R23.2
N$51
  Bottom 0.406: SV2.9 82.55,34.29 80.01,36.83 RN4.7 80.01,38.73 R24.2
N$52
  Bottom 0.305: 81.28,27.31 81.28,33.02
  Bottom 0.406: 81.28,27.31 SV2.10 | 81.28,33.02 77.47,36.83 RN4.6 77.47,38.73 R25.2
N$53
  Bottom 0.406: SV2.11 80.01,32.38 RN4.5 74.93,38.73 R26.2
N$54
  Bottom 0.305: 78.74,31.75 78.74,27.31
  Bottom 0.406: 78.74,27.31 SV2.12 | 78.74,31.75 74.93,35.56 73.03,35.56 72.39,36.2 RN4.4 72.39,38.73 R27.2
N$55
  Bottom 0.406: SV2.13 77.47,31.12 74.93,33.66 71.12,33.66 69.85,34.92 RN4.3 69.85,38.73 R28.2
N$56
  Bottom 0.305: 76.2,30.48 76.2,27.31
  Bottom 0.406: 76.2,27.31 SV2.14 | 76.2,30.48 74.93,31.75 69.85,31.75 67.31,34.29 RN4.2 67.31,38.73 R29.2
N$57
  Bottom 0.305: 140.97,59.05 140.97,65.41
  Bottom 0.406: IC7.7 140.97,59.05 | 140.97,65.41 139.7,66.68 IC3.7
N$58
  Bottom 0.305: 143.51,59.05 143.51,65.41
  Bottom 0.406: IC7.6 143.51,59.05 | 143.51,65.41 142.24,66.68 IC3.6
N$59
  Bottom 0.305: 146.05,59.05 146.05,65.41
  Bottom 0.406: IC7.4 146.05,59.05 | 146.05,65.41 144.78,66.68 IC3.5
N$60
  Bottom 0.305: 151.13,60.32 151.13,62.86
  Bottom 0.406: IC7.1 153.03,59.69 151.76,59.69 151.13,60.32 | 151.13,62.86 147.32,66.68 IC3.4
N$61
  Bottom 0.406: IC7.5 IC3.12
N$62
  Bottom 0.406: IC7.3 147.32,60.32 IC3.13
N$63
  Bottom 0.406: IC7.2 149.86,60.32 IC3.14
N$64
  Bottom 0.406: IC8.2 127,60.32 IC5.14
N$65
  Bottom 0.305: 128.27,60.32 128.27,62.86
  Bottom 0.406: IC8.1 130.17,59.69 128.91,59.69 128.27,60.32 | 128.27,62.86 124.46,66.68 IC5.4
N$66
  Bottom 0.305: 118.11,59.05 118.11,64.14
  Bottom 0.406: IC8.7 118.11,59.05 | 118.11,64.14 116.84,65.41 IC5.7
N$67
  Bottom 0.305: 120.65,59.05 120.65,65.41
  Bottom 0.406: IC8.6 120.65,59.05 | 120.65,65.41 119.38,66.68 IC5.6
N$68
  Bottom 0.305: 123.19,59.05 123.19,65.41
  Bottom 0.406: IC8.4 123.19,59.05 | 123.19,65.41 121.92,66.68 IC5.5
N$69
  Bottom 0.406: IC8.5 IC5.12
N$70
  Bottom 0.406: IC8.3 124.46,60.32 IC5.13
N$71
  Bottom 0.406: IC9.1 102.23,59.69 100.97,59.69 100.33,60.32 100.33,62.86 96.52,66.68 IC6.4
N$72
  Bottom 0.406: IC9.4 95.25,59.05 95.25,65.41 93.98,66.68 IC6.5
N$73
  Bottom 0.406: IC9.6 92.71,59.05 92.71,65.41 91.44,66.68 IC6.6
N$74
  Bottom 0.406: IC9.7 90.17,59.05 90.17,65.41 88.9,66.68 IC6.7
N$75
  Bottom 0.406: IC9.2 99.06,60.32 IC6.14
N$76
  Bottom 0.406: IC9.3 96.52,60.32 IC6.13
N$77
  Bottom 0.406: IC9.5 IC6.12
N$78
  Bottom 0.305: 77.47,60.32 77.47,62.86
  Bottom 0.406: IC10.1 79.38,59.69 78.11,59.69 77.47,60.32 | 77.47,62.86 73.66,66.68 IC11.4
N$79
  Bottom 0.305: 72.39,59.05 72.39,65.41
  Bottom 0.406: IC10.4 72.39,59.05 | 72.39,65.41 71.12,66.68 IC11.5
N$80
  Bottom 0.305: 69.85,59.05 69.85,65.41
  Bottom 0.406: IC10.6 69.85,59.05 | 69.85,65.41 68.58,66.68 IC11.6
N$81
  Bottom 0.305: 67.31,59.05 67.31,64.14
  Bottom 0.406: IC10.7 67.31,59.05 | 67.31,64.14 66.04,65.41 IC11.7
N$82
  Bottom 0.406: IC2.3 C8.1
N$83
  Bottom 0.406: IC2.2 7.62,26.04 7.62,29.85 | 7.62,29.85 6.35,31.12 Q2.B | 7.62,29.85 10.16,29.85 11.43,28.58 R36.2
N$84
  Bottom 0.406: D1.A 10.16,32.38 7.62,32.38 6.35,33.66
  Bottom 0.813: Q2.C 6.35,33.66 L1.2
N$85
  Bottom 0.406: IC10.2 76.2,60.32 IC11.14
N$86
  Bottom 0.406: R52.S 12.7,6.98 6.35,13.33 C9.1 3.17,15.88 IC2.5
N$87
  Bottom 0.406: R52.A 15.88,13.33 13.33,15.88 R34.1
N$88
  Bottom 0.305: 4.45,17.15 4.45,21.59 | 9.53,24.13 9.53,26.67
  Bottom 0.406: 4.45,17.15 9.53,12.06 R52.E | 4.45,21.59 5.71,22.86 8.26,22.86 9.53,24.13 | 9.53,26.67 R35.2
N$89
  Bottom 0.406: IC10.3 73.66,60.32 IC11.13
N$90
  Bottom 0.406: C21.1 5.84,17.91 IC2.6
  Bottom 0.813: IC2.7 IC2.6 | IC2.7 IC2.8 IC2.1 15.88,25.4 17.15,26.67 17.15,28.58 15.88,29.85 15.88,33.02 C7.1 6.35,42.54 L1.1 | L1.1 10.79,57.78 C5.+ | JP1.3 17.15,6.35 12.7,10.79 12.7,12.7 11.43,13.97 9.53,13.97 8.26,15.24 IC2.7 | IC4.IN C11.1 L1.1
N$91
  Bottom 0.406: IC10.5 IC11.12
N$92
  Bottom 0.406: SV2.15 73.66,29.85 66.04,29.85 60.96,34.92 60.96,45.09 59.69,46.35 R30.2
N$93
  Bottom 0.406: IC3.9 137.16,64.77 135.25,66.68 130.81,66.68 129.54,67.95 IC5.2
N$94
  Bottom 0.406: IC5.9 114.3,64.14 111.12,67.31 102.23,67.31 101.6,67.95 IC6.2
N$95
  Bottom 0.406: IC6.9 86.36,64.77 84.45,66.68 80.01,66.68 78.74,67.95 IC11.2
N$96  (via drill 0.61 pad 1.42)
  Top 0.406: v127,76.84 v127,73.03 | v99.06,76.84 v99.06,73.03 | v76.2,76.84 v76.2,73.03
  Bottom 0.305: SV3.7 52.07,47.62
  Bottom 0.406: IC3.3 149.86,71.12 144.14,76.84 v127,76.84 v99.06,76.84 v76.2,76.84 55.88,76.84 52.07,73.03 52.07,60.32 53.34,59.05 53.34,55.24 49.53,51.43 IC1.19 52.07,47.62 | v127,73.03 IC5.3 | v99.06,73.03 IC6.3 | v76.2,73.03 IC11.3
N$97  (via drill 0.61 pad 1.42)
  Top 0.406: v132.08,78.74 v132.08,73.03 | v104.14,78.74 v104.14,73.03 | v81.28,78.74 v81.28,73.03
  Bottom 0.406: v132.08,73.03 IC5.1 | IC3.1 153.03,71.12 151.76,71.12 144.14,78.74 v132.08,78.74 v104.14,78.74 v81.28,78.74 55.24,78.74 50.8,74.3 50.8,56.52 48.26,53.98 43.18,53.98 41.91,52.7 IC1.16 | v104.14,73.03 IC6.1 | v81.28,73.03 IC11.1
N$98
  Bottom 0.406: R15.1 110.49,57.78 111.76,59.05 T1.C
N$99
  Bottom 0.406: R30.1 60.96,59.05 T2.C
N$100
  Bottom 0.406: T1.B R31.2
N$101
  Bottom 0.406: T2.B R32.2
N$102
  Bottom 0.305: 118.11,66.04 118.11,71.76
  Bottom 0.406: R31.1 116.84,73.03 118.11,71.76 | 118.11,66.04 119.38,64.77 IC5.11
N$103
  Bottom 0.305: 67.31,71.76 67.31,66.04
  Bottom 0.406: R32.1 66.04,73.03 67.31,71.76 | 67.31,66.04 68.58,64.77 IC11.11
N$104
  Bottom 0.406: T5.C R33.1
N$105
  Bottom 0.406: R33.2 67.31,23.5 66.04,22.23 T8.B 66.04,17.15 67.31,15.88 R38.1
N$106
  Bottom 0.406: T4.C R39.1
N$107
  Bottom 0.406: R40.1 114.3,26.04 113.03,27.31 T7.B 113.03,32.38 114.3,33.66 R39.2
N$108
  Bottom 0.406: T3.C R41.1
N$109
  Bottom 0.406: R42.1 114.3,15.88 113.03,17.15 T6.B 113.03,22.23 114.3,23.5 R41.2
N$110
  Bottom 0.406: T5.B 58.42,22.23 55.88,24.77 R43.1
N$111
  Bottom 0.406: R44.1 57.15,41.27 57.15,31.12 62.23,26.04 68.58,26.04 78.74,15.88 105.41,15.88 106.68,17.15 106.68,27.31 105.41,28.58 T4.B
N$112  (via drill 0.61 pad 1.42)
  Top 0.406: v107.95,13.33 v115.57,13.33
  Bottom 0.406: T8.C 74.93,13.33 v107.95,13.33 | v115.57,13.33 156.21,13.33 157.48,14.61 JP2.3
N$113
  Bottom 0.406: T7.C 116.84,29.85 119.38,27.31 119.38,23.5 121.92,20.96 146.05,20.96 149.86,24.77 149.86,27.31 151.13,28.58 153.67,28.58 154.94,27.31 JP2.2
N$114
  Bottom 0.406: T6.C 151.13,19.69 152.4,20.96 JP2.1
N$115
  Bottom 0.406: R45.1 58.42,42.54 58.42,32.38 63.5,27.31 68.58,27.31 78.74,17.15 104.14,17.15 105.41,18.42 T3.B
N$116
  Bottom 0.406: SV1.15 123.19,28.58 116.2,35.56 111.12,35.56 109.22,37.46 R15.2
N$117
  Bottom 0.305: SV3.5 53.34,10.79 48.26,10.79 47.62,11.43 47.62,13.33 49.53,15.24 49.53,37.46 49.53,45.72 | 43.18,48.26 43.18,51.43
  Bottom 0.406: 49.53,45.72 48.26,46.99 44.45,46.99 43.18,48.26 | 43.18,51.43 44.45,52.7 48.89,52.7 52.07,55.88 IC1.1 | 49.53,37.46 R46.2 45.72,38.73 44.45,40 C1.2
N$118  (via drill 0.61 pad 1.42)
  Top 0.406: v26.67,50.16 v26.67,59.69
  Bottom 0.406: v26.67,59.69 27.31,60.32 31.75,60.32 34.29,62.86 34.29,70.48 31.75,73.03 24.13,73.03 21.59,75.57 21.59,76.45 S3.2 | IC1.11 v26.67,50.16
N$119
  Bottom 0.406: R45.2 46.99,43.81 39.37,43.81 36.83,46.35 IC1.14
N$120
  Bottom 0.406: IC1.13 34.29,47.62 39.37,42.54 R44.2
N$121
  Bottom 0.406: IC1.12 31.75,48.89 39.37,41.27 46.99,41.27 R43.2
N$122  (via drill 0.61 pad 1.42)
  Top 0.406: v50.8,33.66 v64.77,33.66
  Bottom 0.305: v50.8,33.66 50.8,46.35
  Bottom 0.406: SV3.9 50.8,13.33 v50.8,33.66 | 50.8,46.35 IC1.18 | IC3.2 152.4,67.95 153.67,66.68 156.21,66.68 158.75,64.14 158.75,55.24 157.48,53.98 63.5,53.98 61.59,52.07 61.59,46.35 62.23,45.72 62.23,36.2 v64.77,33.66
N$123
  Bottom 0.406: U4.2 18.42,42.54 19.05,43.18 19.05,48.89 18.42,49.53 IC17.2
N$124
  Bottom 0.406: S2.2 35.56,72.64 35.56,61.59 IC1.9
N$125
  Bottom 0.406: IC1.4 44.45,61.72 Q1.2 46.99,64.26 C2.2
N$126
  Bottom 0.406: IC1.5 41.91,61.72 Q1.1 39.37,64.26 C3.2
N$127
  Bottom 0.406: S1.2 41.91,76.45 41.91,74.3 36.83,69.22 36.83,60.32 IC1.8
N$128
  Bottom 0.406: R50.1 C17.1 R49.2
N$129
  Bottom 0.406: T9.B 27.94,41.27 30.48,43.81 R51.2
N$130
  Bottom 0.406: C18.1 R50.2 R51.1
N$131
  Bottom 0.406: C19.+ T9.C
N$132
  Bottom 0.406: JP3.1 17.78,38.73 C19.-
N$133
  Bottom 0.406: R49.1 39.37,46.35 IC1.15
N$134  (via drill 0.61 pad 1.42)
  Top 0.406: v55.24,48.26 v45.72,48.26
  Bottom 0.305: 54.61,16.51 54.61,47.62
  Bottom 0.406: SV3.1 59.69,13.33 57.78,15.24 55.88,15.24 54.61,16.51 | 54.61,47.62 v55.24,48.26 | v45.72,48.26 44.45,49.53 IC1.17
N$135
  Bottom 0.406: IC17.1 16.51,48.26 U4.1
N$136
  Bottom 0.406: IC17.3 18.42,50.8 19.05,51.43 19.05,55.88 21.59,58.42 G1.+
N$137
  Bottom 0.406: IC1.2 46.99,55.24 41.91,55.24 40,53.34 24.13,53.34 23.39,52.6 IC17.5
N$138
  Bottom 0.406: IC1.3 45.72,56.52 40.64,56.52 38.73,54.61 22.86,54.61 21.59,53.34 21.59,51.43 22.23,50.8 IC17.6
N$139  (via drill 0.61 pad 1.42)
  other vias: 22.86,45.09
N$140  (via drill 0.61 pad 1.42)
  other vias: 22.86,42.54
N$141  (via drill 0.61 pad 1.68)
  other vias: 5.71,5.71
N$142  (via drill 0.61 pad 1.68)
  other vias: 5.71,75.57
N$143  (via drill 0.61 pad 1.68)
  other vias: 154.3,75.57
N$144  (via drill 0.61 pad 1.68)
  other vias: 154.3,5.71
VCC  (via drill 0.61 pad 1.42)
  Top 0.406: v20.32,5.08 v43.18,5.08
  Bottom 0.406: 110.49,15.88 T6.E 110.49,26.04 | 110.49,26.04 T7.E | 110.49,26.04 R40.2 | 110.49,15.88 R42.2 | T8.E 62.23,18.42 R38.2 63.5,15.88 66.04,13.33 66.04,8.89 | 66.04,8.89 62.23,5.08 v43.18,5.08 | 66.04,8.89 106.68,8.89 110.49,12.7 110.49,15.88 | C4.+ 19.05,26.67 14.61,22.23 D1.C 16.51,15.88 R34.2 19.05,15.24 C16.+ 19.05,6.35 | R47.2 19.05,6.35 | 19.05,6.35 v20.32,5.08
VCC/2
  Bottom 0.305: 111.76,10.79 111.76,32.38
  Bottom 0.406: 86.36,52.07 IC9.9 RN3.1 | 86.36,52.07 65.41,52.07 IC10.9 63.5,38.73 RN4.1 | 114.3,52.07 IC8.9 114.3,38.73 RN2.1 | 114.3,52.07 135.25,52.07 IC7.9 RN1.1 | 106.68,52.07 86.36,52.07 | 106.68,52.07 114.3,52.07 | 34.29,3.17 36.2,1.27 43.81,1.27 45.09,2.54 62.86,2.54 66.68,6.35 107.32,6.35 111.76,10.79 | C4.- 40.64,31.12 34.29,24.77 34.29,20.96 | 34.29,20.96 C15.+ | 34.29,3.17 34.29,20.96 | 111.76,32.38 106.68,37.46 106.68,52.07 | R47.1 R48.2 34.29,3.17

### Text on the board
Bottom: Nixie Clock Controller | for Burroughs B7971 | (C) 2004 by Thorsten.Erdmann@gmx.de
